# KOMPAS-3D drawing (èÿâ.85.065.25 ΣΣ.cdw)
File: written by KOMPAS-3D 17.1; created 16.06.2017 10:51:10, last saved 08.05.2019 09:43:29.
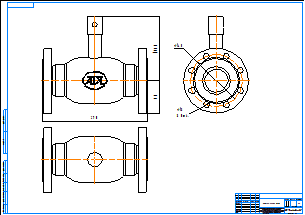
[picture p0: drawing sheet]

Sheet 1: A1, landscape

Title block, sheet 1: name: КШГ.85.065.25 фф; material: Внимание! Данный продукт является объектом авторского права ООО «Торговый Дом АДЛ». / Запрещается изменение, копирование, распространение / (в том числе путем копирования на другие сайты и ресурсы в Интернете) / или любое иное использование информации и объектов без предварительного / согласия правообладателя (ООО «Торговый Дом АДЛ»).; scale: 1:1; sheets: 1; organisation: ООО "Торговый дом АДЛ"; sheet format: A1; stored path: C:\Users\tra\Desktop\2д чертежи\Шаровые краны БИВАЛ\КШ_Бивал_серия_82_85\KOMPAS 2D\КШГ.85.065.25 фф.cdw

Views: Спереди 1, Проекционный вид 2, Проекционный вид 3
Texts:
  Klimkovich
  ADL
Dimensions and other numbers on the sheet: 290; 176,8; 90; 145; 18; 8 Отв.; 1:1; 1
